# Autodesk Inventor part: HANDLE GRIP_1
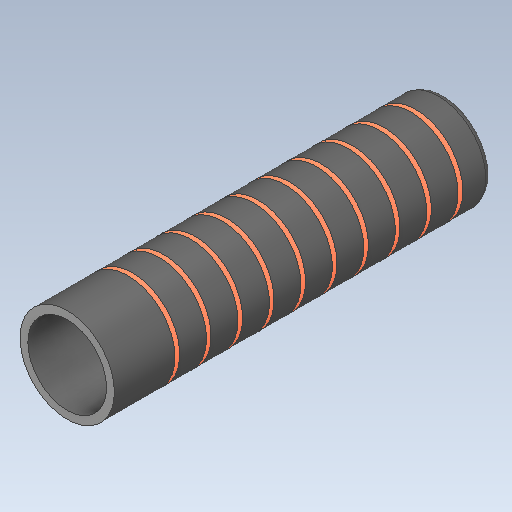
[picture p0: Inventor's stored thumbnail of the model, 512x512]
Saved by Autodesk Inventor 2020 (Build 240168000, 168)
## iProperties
Created: 1900-01
Part Number: HANDLE GRIP_1
Material: Générique
Document SubType Name: Modeling
Designer: bruno
Density: 1 g/cm^3
Appearance: Par défaut
Author: bruno
Revision Number: ANYUNSPECIFIED
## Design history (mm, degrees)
feature "Base1"
node "Solide1"
